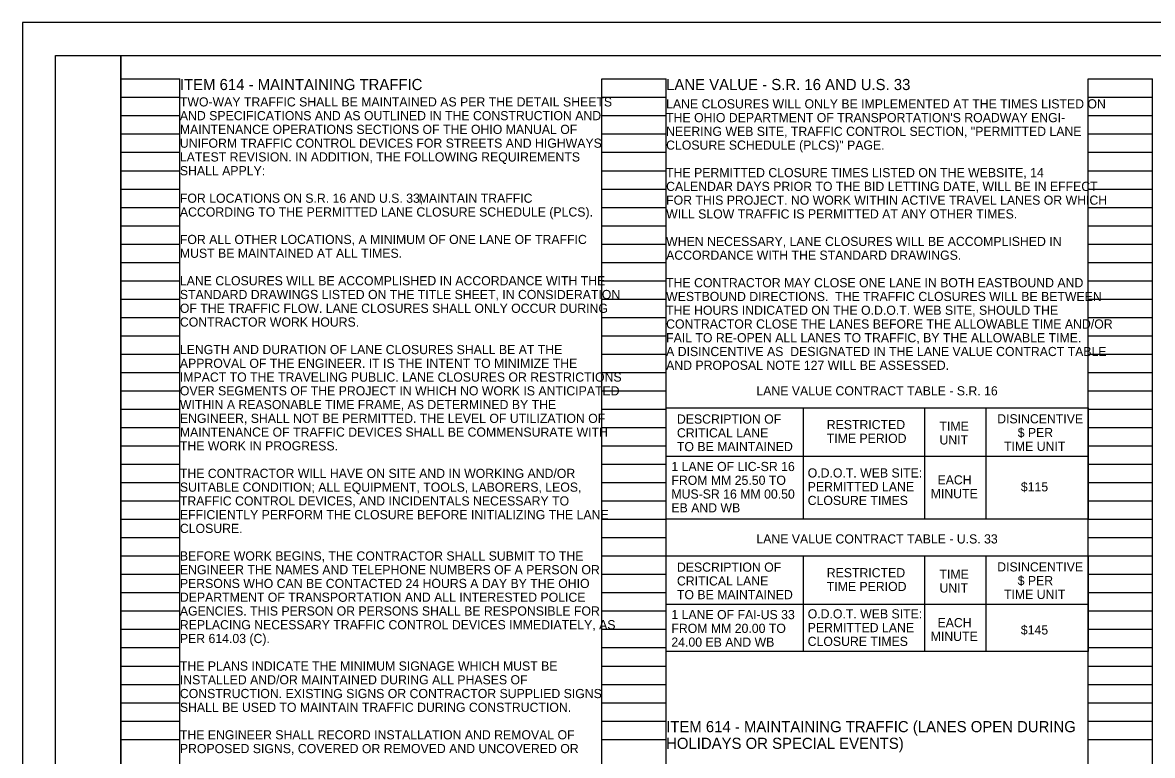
# Model space of a CAD drawing. Extents: x 0 to 34, y 0 to 22.
# Drawn here: x 0 to 17.24, y 10.82 to 22 of the extents above; entities that cross this region are included whole.
import ezdxf

# ---------------------------------------------------------------- set-up
doc = ezdxf.new("R2010")
doc.units = 0
for name, color, linetype in [('SH_Border', 7, 'Continuous'), ('SH_Cut_Line', 7, 'Continuous'), ('SH_Data', 7, 'Continuous'), ('SH_Text', 7, 'Continuous')]:
    doc.layers.add(name, color=color, linetype=linetype)

msp = doc.modelspace()

# ---------------------------------------------------------------- linework, layer by layer
at = {"layer": 'SH_Border'}
for points in [[(0.5, 21.5), (1.5, 21.5), (1.5, 0.5), (0.5, 0.5)], [(1.5, 21.5), (33.5, 21.5), (33.5, 0.5), (1.5, 0.5)]]:
    msp.add_lwpolyline(points, close=True, dxfattribs=at)
at = {"layer": 'SH_Cut_Line'}
msp.add_lwpolyline([(0, 0), (34, 0), (34, 22), (0, 22)], close=True, dxfattribs=at)
at = {"layer": 'SH_Data'}
for p, q in [((1.5, 0.98), (1.5, 21.14)), ((1.5, 21.14), (2.4, 21.14)), ((2.4, 0.98), (2.4, 21.14)), ((8.84, 0.98), (8.84, 21.14)), ((8.84, 21.14), (9.82, 21.14)), ((9.82, 0.98), (9.82, 21.14)), ((16.26, 0.98), (16.26, 21.14)), ((16.26, 21.14), (17.24, 21.14)), ((17.24, 0.98), (17.24, 21.14)), ((1.5, 20.86), (2.4, 20.86)), ((8.84, 20.86), (9.82, 20.86)), ((16.26, 20.86), (17.24, 20.86)), ((1.5, 20.58), (2.4, 20.58)), ((8.84, 20.58), (9.82, 20.58)), ((16.26, 20.58), (17.24, 20.58)), ((1.5, 20.3), (2.4, 20.3)), ((8.84, 20.3), (9.82, 20.3)), ((16.26, 20.3), (17.24, 20.3)), ((1.5, 20.02), (2.4, 20.02)), ((8.84, 20.02), (9.82, 20.02)), ((16.26, 20.02), (17.24, 20.02)), ((1.5, 19.74), (2.4, 19.74)), ((8.84, 19.74), (9.82, 19.74)), ((16.26, 19.74), (17.24, 19.74)), ((1.5, 19.46), (2.4, 19.46)), ((8.84, 19.46), (9.82, 19.46)), ((16.26, 19.46), (17.24, 19.46)), ((1.5, 19.18), (2.4, 19.18)), ((8.84, 19.18), (9.82, 19.18)), ((16.26, 19.18), (17.24, 19.18)), ((1.5, 18.9), (2.4, 18.9)), ((8.84, 18.9), (9.82, 18.9)), ((16.26, 18.9), (17.24, 18.9)), ((1.5, 18.62), (2.4, 18.62)), ((8.84, 18.62), (9.82, 18.62)), ((16.26, 18.62), (17.24, 18.62)), ((1.5, 18.34), (2.4, 18.34)), ((8.84, 18.34), (9.82, 18.34)), ((16.26, 18.34), (17.24, 18.34)), ((1.5, 18.06), (2.4, 18.06)), ((8.84, 18.06), (9.82, 18.06)), ((16.26, 18.06), (17.24, 18.06)), ((1.5, 17.78), (2.4, 17.78)), ((8.84, 17.78), (9.82, 17.78)), ((16.26, 17.78), (17.24, 17.78)), ((1.5, 17.5), (2.4, 17.5)), ((8.84, 17.5), (9.82, 17.5)), ((16.26, 17.5), (17.24, 17.5)), ((1.5, 17.22), (2.4, 17.22)), ((8.84, 17.22), (9.82, 17.22)), ((16.26, 17.22), (17.24, 17.22)), ((1.5, 16.94), (2.4, 16.94)), ((8.84, 16.94), (9.82, 16.94)), ((16.26, 16.94), (17.24, 16.94)), ((1.5, 16.66), (2.4, 16.66)), ((8.84, 16.66), (9.82, 16.66)), ((16.26, 16.66), (17.24, 16.66)), ((1.5, 16.38), (2.4, 16.38)), ((8.84, 16.38), (9.82, 16.38)), ((16.26, 16.38), (17.24, 16.38)), ((1.5, 16.1), (2.4, 16.1)), ((8.84, 16.1), (9.82, 16.1)), ((16.26, 16.1), (17.24, 16.1)), ((1.5, 15.82), (2.4, 15.82)), ((8.84, 15.82), (9.82, 15.82)), ((16.26, 15.82), (17.24, 15.82)), ((1.5, 15.54), (2.4, 15.54)), ((8.84, 15.54), (9.82, 15.54)), ((16.26, 15.54), (17.24, 15.54)), ((1.5, 15.26), (2.4, 15.26)), ((8.84, 15.26), (9.82, 15.26)), ((16.26, 15.26), (17.24, 15.26)), ((1.5, 14.98), (2.4, 14.98)), ((8.84, 14.98), (9.82, 14.98)), ((16.26, 14.98), (17.24, 14.98)), ((1.5, 14.7), (2.4, 14.7)), ((8.84, 14.7), (9.82, 14.7)), ((16.26, 14.7), (17.24, 14.7)), ((1.5, 14.42), (2.4, 14.42)), ((8.84, 14.42), (9.82, 14.42)), ((16.26, 14.42), (17.24, 14.42)), ((1.5, 14.14), (2.4, 14.14)), ((8.84, 14.14), (9.82, 14.14)), ((16.26, 14.14), (17.24, 14.14)), ((1.5, 13.86), (2.4, 13.86)), ((8.84, 13.86), (9.82, 13.86)), ((16.26, 13.86), (17.24, 13.86)), ((1.5, 13.58), (2.4, 13.58)), ((8.84, 13.58), (9.82, 13.58)), ((16.26, 13.58), (17.24, 13.58)), ((1.5, 13.3), (2.4, 13.3)), ((8.84, 13.3), (9.82, 13.3)), ((16.26, 13.3), (17.24, 13.3)), ((1.5, 13.02), (2.4, 13.02)), ((8.84, 13.02), (9.82, 13.02)), ((16.26, 13.02), (17.24, 13.02)), ((1.5, 12.74), (2.4, 12.74)), ((8.84, 12.74), (9.82, 12.74)), ((16.26, 12.74), (17.24, 12.74)), ((1.5, 12.46), (2.4, 12.46)), ((8.84, 12.46), (9.82, 12.46)), ((16.26, 12.46), (17.24, 12.46)), ((1.5, 12.18), (2.4, 12.18)), ((8.84, 12.18), (9.82, 12.18)), ((16.26, 12.18), (17.24, 12.18)), ((1.5, 11.9), (2.4, 11.9)), ((8.84, 11.9), (9.82, 11.9)), ((16.26, 11.9), (17.24, 11.9)), ((1.5, 11.62), (2.4, 11.62)), ((8.84, 11.62), (9.82, 11.62)), ((16.26, 11.62), (17.24, 11.62)), ((1.5, 11.34), (2.4, 11.34)), ((8.84, 11.34), (9.82, 11.34)), ((16.26, 11.34), (17.24, 11.34)), ((1.5, 11.06), (2.4, 11.06)), ((8.84, 11.06), (9.82, 11.06)), ((16.26, 11.06), (17.24, 11.06))]:
    msp.add_line(p, q, dxfattribs=at)
at = {"layer": 'SH_Text'}
for p, q in [((11.914, 14.42), (11.914, 16.12)), ((13.766, 14.42), (13.766, 16.12)), ((14.705, 14.42), (14.705, 16.12)), ((9.82, 15.382), (16.26, 15.382)), ((11.914, 12.402), (11.914, 13.86)), ((13.766, 12.402), (13.766, 13.86)), ((14.705, 12.402), (14.705, 13.86)), ((9.82, 13.122), (16.26, 13.122))]:
    msp.add_line(p, q, dxfattribs=at)
for points in [[(9.82, 16.12), (16.26, 16.12), (16.26, 14.42), (9.82, 14.42)], [(9.82, 13.86), (16.26, 13.86), (16.26, 12.402), (9.82, 12.402)]]:
    msp.add_lwpolyline(points, close=True, dxfattribs=at)

# ---------------------------------------------------------------- texts
for s, height, p in [('ITEM 614 - MAINTAINING TRAFFIC', 0.17, (2.4, 20.97)), ('LANE VALUE - S.R. 16 AND U.S. 33', 0.17, (9.82, 20.97)), ('TWO-WAY TRAFFIC SHALL BE MAINTAINED AS PER THE DETAIL SHEETS ', 0.14, (2.4, 20.72)), ('LANE CLOSURES WILL ONLY BE IMPLEMENTED AT THE TIMES LISTED ON ', 0.14, (9.82, 20.69)), ('AND SPECIFICATIONS AND AS OUTLINED IN THE CONSTRUCTION AND ', 0.14, (2.4, 20.51)), ("THE OHIO DEPARTMENT OF TRANSPORTATION'S ROADWAY ENGI-", 0.14, (9.82, 20.48)), ('MAINTENANCE OPERATIONS SECTIONS OF THE OHIO MANUAL OF ', 0.14, (2.4, 20.3)), ('NEERING WEB SITE, TRAFFIC CONTROL SECTION, "PERMITTED LANE ', 0.14, (9.82, 20.27)), ('UNIFORM TRAFFIC CONTROL DEVICES FOR STREETS AND HIGHWAYS ', 0.14, (2.4, 20.09)), ('CLOSURE SCHEDULE (PLCS)" PAGE.', 0.14, (9.82, 20.06)), ('LATEST REVISION. IN ADDITION, THE FOLLOWING REQUIREMENTS ', 0.14, (2.4, 19.88)), ('SHALL APPLY:', 0.14, (2.4, 19.67)), ('THE PERMITTED CLOSURE TIMES LISTED ON THE WEBSITE, 14 ', 0.14, (9.82, 19.64)), ('CALENDAR DAYS PRIOR TO THE BID LETTING DATE, WILL BE IN EFFECT ', 0.14, (9.82, 19.43)), ('FOR LOCATIONS ON S.R. 16 AND U.S. 33, ', 0.14, (2.4, 19.25)), ('MAINTAIN TRAFFIC ', 0.14, (6.044, 19.25)), ('FOR THIS PROJECT. NO WORK WITHIN ACTIVE TRAVEL LANES OR WHICH ', 0.14, (9.82, 19.22)), ('ACCORDING TO THE PERMITTED LANE CLOSURE SCHEDULE (PLCS).', 0.14, (2.4, 19.04)), ('WILL SLOW TRAFFIC IS PERMITTED AT ANY OTHER TIMES.', 0.14, (9.82, 19.01)), ('FOR ALL OTHER LOCATIONS, A MINIMUM OF ONE LANE OF TRAFFIC ', 0.14, (2.4, 18.62)), ('WHEN NECESSARY, LANE CLOSURES WILL BE ACCOMPLISHED IN ', 0.14, (9.82, 18.59)), ('MUST BE MAINTAINED AT ALL TIMES.', 0.14, (2.4, 18.41)), ('ACCORDANCE WITH THE STANDARD DRAWINGS.  ', 0.14, (9.82, 18.38)), ('LANE CLOSURES WILL BE ACCOMPLISHED IN ACCORDANCE WITH THE ', 0.14, (2.4, 17.99)), ('THE CONTRACTOR MAY CLOSE ONE LANE IN BOTH EASTBOUND AND', 0.14, (9.82, 17.96)), ('STANDARD DRAWINGS LISTED ON THE TITLE SHEET, IN CONSIDERATION ', 0.14, (2.4, 17.78)), ('WESTBOUND DIRECTIONS.  THE TRAFFIC CLOSURES WILL BE BETWEEN', 0.14, (9.82, 17.75)), ('OF THE TRAFFIC FLOW. LANE CLOSURES SHALL ONLY OCCUR DURING ', 0.14, (2.4, 17.57)), ('THE HOURS INDICATED ON THE O.D.O.T. WEB SITE, SHOULD THE', 0.14, (9.82, 17.54)), ('CONTRACTOR WORK HOURS.', 0.14, (2.4, 17.36)), ('CONTRACTOR CLOSE THE LANES BEFORE THE ALLOWABLE TIME AND/OR', 0.14, (9.82, 17.33)), ('FAIL TO RE-OPEN ALL LANES TO TRAFFIC, BY THE ALLOWABLE TIME.', 0.14, (9.82, 17.12)), ('LENGTH AND DURATION OF LANE CLOSURES SHALL BE AT THE ', 0.14, (2.4, 16.94)), ('A DISINCENTIVE AS  DESIGNATED IN THE LANE VALUE CONTRACT TABLE', 0.14, (9.82, 16.91)), ('APPROVAL OF THE ENGINEER. IT IS THE INTENT TO MINIMIZE THE ', 0.14, (2.4, 16.73)), ('AND PROPOSAL NOTE 127 WILL BE ASSESSED.  ', 0.14, (9.82, 16.7)), ('IMPACT TO THE TRAVELING PUBLIC. LANE CLOSURES OR RESTRICTIONS ', 0.14, (2.4, 16.52)), ('OVER SEGMENTS OF THE PROJECT IN WHICH NO WORK IS ANTICIPATED', 0.14, (2.4, 16.31)), ('LANE VALUE CONTRACT TABLE - S.R. 16', 0.14, (11.197, 16.31)), ('WITHIN A REASONABLE TIME FRAME, AS DETERMINED BY THE ', 0.14, (2.4, 16.1)), ('ENGINEER, SHALL NOT BE PERMITTED. THE LEVEL OF UTILIZATION OF ', 0.14, (2.4, 15.89)), ('DESCRIPTION OF ', 0.14, (9.985, 15.879)), ('RESTRICTED ', 0.14, (12.271, 15.795)), ('TIME ', 0.14, (13.991, 15.771)), ('DISINCENTIVE', 0.14, (14.872, 15.883)), ('MAINTENANCE OF TRAFFIC DEVICES SHALL BE COMMENSURATE WITH ', 0.14, (2.4, 15.68)), ('CRITICAL LANE', 0.14, (9.985, 15.669)), ('TIME PERIOD', 0.14, (12.271, 15.585)), ('UNIT', 0.14, (13.991, 15.561)), ('      $ PER ', 0.14, (14.872, 15.673)), ('THE WORK IN PROGRESS.', 0.14, (2.4, 15.47)), ('TO BE MAINTAINED', 0.14, (9.985, 15.459)), ('  TIME UNIT', 0.14, (14.872, 15.463)), ('THE CONTRACTOR WILL HAVE ON SITE AND IN WORKING AND/OR ', 0.14, (2.4, 15.05)), ('1 LANE OF LIC-SR 16', 0.14, (9.9, 15.155)), ('O.D.O.T. WEB SITE:', 0.14, (11.98, 15.057)), ('FROM MM 25.50 TO ', 0.14, (9.9, 14.945)), ('  EACH', 0.14, (13.857, 14.951)), ('SUITABLE CONDITION; ALL EQUIPMENT, TOOLS, LABORERS, LEOS, ', 0.14, (2.4, 14.84)), ('MUS-SR 16 MM 00.50 ', 0.14, (9.9, 14.735)), ('PERMITTED LANE ', 0.14, (11.98, 14.847)), ('MINUTE', 0.14, (13.857, 14.741)), ('$115', 0.14, (15.233, 14.845)), ('TRAFFIC CONTROL DEVICES, AND INCIDENTALS NECESSARY TO ', 0.14, (2.4, 14.63)), ('EB AND WB', 0.14, (9.9, 14.525)), ('CLOSURE TIMES', 0.14, (11.98, 14.637)), ('EFFICIENTLY PERFORM THE CLOSURE BEFORE INITIALIZING THE LANE ', 0.14, (2.4, 14.42)), ('CLOSURE.', 0.14, (2.4, 14.21)), ('LANE VALUE CONTRACT TABLE - U.S. 33', 0.14, (11.197, 14.05)), ('BEFORE WORK BEGINS, THE CONTRACTOR SHALL SUBMIT TO THE ', 0.14, (2.4, 13.79)), ('ENGINEER THE NAMES AND TELEPHONE NUMBERS OF A PERSON OR ', 0.14, (2.4, 13.58)), ('DESCRIPTION OF ', 0.14, (9.985, 13.619)), ('RESTRICTED ', 0.14, (12.271, 13.534)), ('TIME ', 0.14, (13.991, 13.511)), ('DISINCENTIVE', 0.14, (14.872, 13.623)), ('PERSONS WHO CAN BE CONTACTED 24 HOURS A DAY BY THE OHIO ', 0.14, (2.4, 13.37)), ('CRITICAL LANE', 0.14, (9.985, 13.409)), ('TIME PERIOD', 0.14, (12.271, 13.324)), ('      $ PER ', 0.14, (14.872, 13.413)), ('DEPARTMENT OF TRANSPORTATION AND ALL INTERESTED POLICE ', 0.14, (2.4, 13.16)), ('TO BE MAINTAINED', 0.14, (9.985, 13.199)), ('UNIT', 0.14, (13.991, 13.301)), ('  TIME UNIT', 0.14, (14.872, 13.203)), ('AGENCIES. THIS PERSON OR PERSONS SHALL BE RESPONSIBLE FOR ', 0.14, (2.4, 12.95)), ('1 LANE OF FAI-US 33', 0.14, (9.9, 12.895)), ('O.D.O.T. WEB SITE:', 0.14, (11.98, 12.906)), ('REPLACING NECESSARY TRAFFIC CONTROL DEVICES IMMEDIATELY, AS ', 0.14, (2.4, 12.74)), ('FROM MM 20.00 TO  ', 0.14, (9.9, 12.685)), ('PERMITTED LANE ', 0.14, (11.98, 12.696)), ('  EACH', 0.14, (13.857, 12.772)), ('$145', 0.14, (15.233, 12.661)), ('PER 614.03 (C).', 0.14, (2.4, 12.53)), ('24.00 EB AND WB', 0.14, (9.9, 12.475)), ('CLOSURE TIMES', 0.14, (11.98, 12.486)), ('MINUTE', 0.14, (13.857, 12.562)), ('THE PLANS INDICATE THE MINIMUM SIGNAGE WHICH MUST BE ', 0.14, (2.4, 12.11)), ('INSTALLED AND/OR MAINTAINED DURING ALL PHASES OF ', 0.14, (2.4, 11.9)), ('CONSTRUCTION. EXISTING SIGNS OR CONTRACTOR SUPPLIED SIGNS ', 0.14, (2.4, 11.69)), ('SHALL BE USED TO MAINTAIN TRAFFIC DURING CONSTRUCTION.', 0.14, (2.4, 11.48)), ('ITEM 614 - MAINTAINING TRAFFIC (LANES OPEN DURING ', 0.17, (9.82, 11.17)), ('THE ENGINEER SHALL RECORD INSTALLATION AND REMOVAL OF ', 0.14, (2.4, 11.06)), ('HOLIDAYS OR SPECIAL EVENTS)', 0.17, (9.82, 10.915)), ('PROPOSED SIGNS, COVERED OR REMOVED AND UNCOVERED OR ', 0.14, (2.4, 10.85))]:
    msp.add_text(s, height=height, dxfattribs=at).set_placement(p)

doc.saveas('drawing.dxf')
